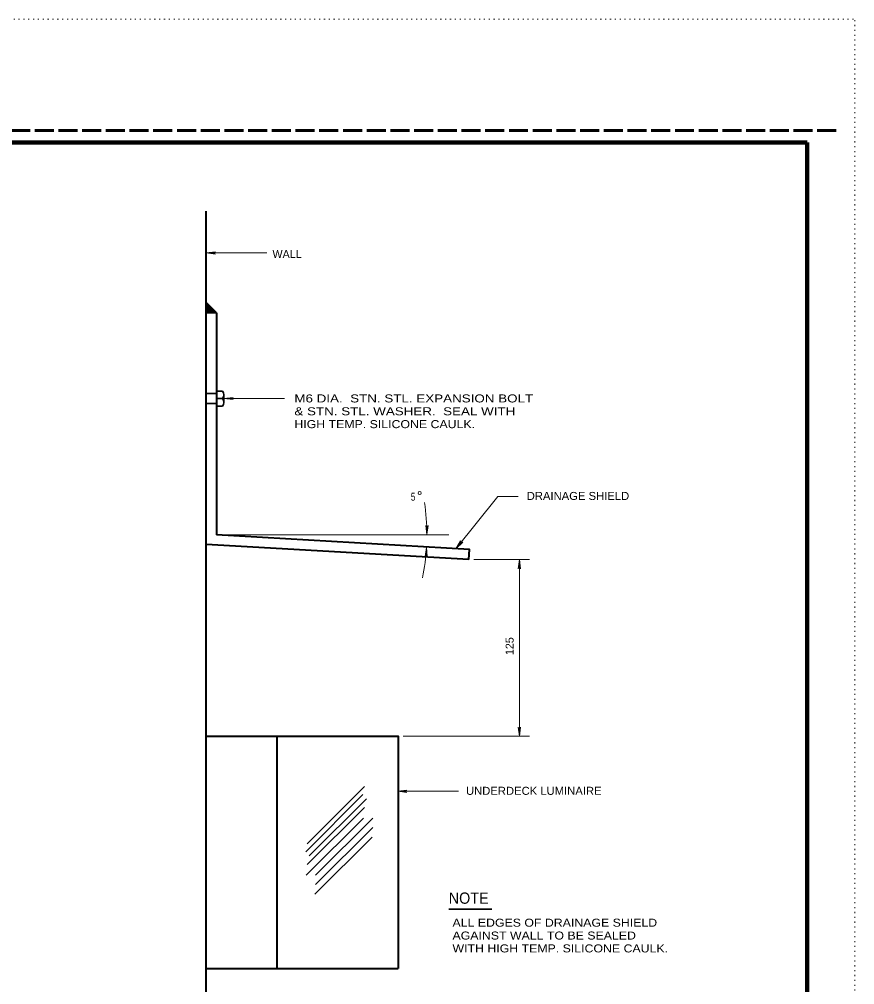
# Model space of a CAD drawing. Extents: x 312583 to 312854, y 144419 to 144597.
# Drawn here: x 312774.2 to 312853.5, y 144505.2 to 144596.8 of the extents above; entities that cross this region are included whole.
import ezdxf
from ezdxf.enums import TextEntityAlignment as Align

# ---------------------------------------------------------------- set-up
doc = ezdxf.new("R2010")
doc.units = 0
doc.header["$LTSCALE"] = 0.3
doc.linetypes.add('DOTTED', pattern=[1.5, 0.3, -1.2])
doc.linetypes.add('LONG_DASHED', pattern=[7.5, 6, -1.5])
for name, color, linetype, lineweight in [('1', 7, 'Continuous', 40), ('2', 7, 'Continuous', 13), ('62', 7, 'DOTTED', 13), ('63', 7, 'LONG_DASHED', 60)]:
    doc.layers.add(name, color=color, linetype=linetype, lineweight=lineweight)

msp = doc.modelspace()

# ---------------------------------------------------------------- linework, layer by layer
at = {"layer": '1', "lineweight": 158}
msp.add_line((312849, 144423.1446), (312849, 144585.0846), dxfattribs=at)
msp.add_lwpolyline([(312616.5, 144423.1446), (312616.5, 144585.0846), (312849, 144585.0846)], dxfattribs=at)
at = {"layer": '2', "lineweight": 40}
for p, q in [((312791.9754, 144501.9119), (312791.9754, 144578.5786)), ((312792.9337, 144568.9339), (312791.9754, 144569.8923)), ((312792.811, 144568.9339), (312791.9754, 144569.7696)), ((312792.673, 144568.9339), (312791.9754, 144569.6316)), ((312792.5197, 144568.9339), (312791.9754, 144569.4783)), ((312792.3817, 144568.9339), (312791.9754, 144569.3403)), ((312792.259, 144568.9339), (312791.9754, 144569.2176)), ((312792.1517, 144568.9339), (312791.9754, 144569.1103)), ((312792.0444, 144568.9339), (312791.9754, 144569.0029)), ((312792.9337, 144568.9339), (312791.9754, 144568.9339)), ((312792.9337, 144568.9339), (312792.9337, 144547.8506)), ((312816.892, 144545.5123), (312791.9754, 144546.9536)), ((312798.6837, 144528.7453), (312798.6837, 144506.7036)), ((312791.9754, 144506.7036), (312810.1837, 144506.7036))]:
    msp.add_line(p, q, dxfattribs=at)
at = {"layer": '2'}
for p, q in [((312791.9677, 144574.6073), (312792.834, 144574.7146)), ((312791.9677, 144574.6073), (312797.7177, 144574.6073)), ((312791.9677, 144574.6073), (312792.834, 144574.4999)), ((312792.834, 144574.7146), (312792.558, 144574.6073)), ((312792.834, 144574.4999), (312792.558, 144574.6073)), ((312792.9337, 144568.9339), (312792.9337, 144561.2673)), ((312793.6544, 144560.7996), (312794.5207, 144560.9069)), ((312793.6544, 144560.7996), (312799.4044, 144560.7996)), ((312793.6544, 144560.7996), (312794.5207, 144560.6923)), ((312794.5207, 144560.9069), (312794.2447, 144560.7996)), ((312794.5207, 144560.6923), (312794.2447, 144560.7996)), ((312815.6654, 144546.5396), (312819.6444, 144551.5076)), ((312819.6444, 144551.5076), (312821.561, 144551.5076)), ((312812.8057, 144548.7399), (312812.913, 144548.4639)), ((312812.913, 144547.8736), (312812.8057, 144548.7399)), ((312813.0204, 144548.7399), (312812.913, 144548.4639)), ((312812.913, 144547.8736), (312813.0204, 144548.7399)), ((312793.409, 144547.8506), (312814.9754, 144547.8506)), ((312812.8824, 144546.6623), (312812.729, 144545.7959)), ((312812.8824, 144546.6623), (312812.9437, 144545.7959)), ((312815.6654, 144546.5396), (312816.11, 144547.2756)), ((312815.6654, 144546.5396), (312816.3094, 144547.1606)), ((312816.11, 144547.2756), (312816.041, 144547.0073)), ((312816.3094, 144547.1606), (312816.041, 144547.0073)), ((312812.729, 144545.7959), (312812.8364, 144546.0719)), ((312812.9437, 144545.7959), (312812.8364, 144546.0719)), ((312817.3674, 144545.5123), (312822.642, 144545.5123)), ((312821.6837, 144545.5123), (312821.5764, 144544.6459)), ((312821.5764, 144544.6459), (312821.6837, 144544.9219)), ((312821.6837, 144528.7453), (312821.6837, 144545.5123)), ((312821.6837, 144545.5123), (312821.791, 144544.6459)), ((312821.791, 144544.6459), (312821.6837, 144544.9219)), ((312821.5764, 144529.6116), (312821.676, 144529.3356)), ((312821.6837, 144528.7453), (312821.5764, 144529.6116)), ((312821.791, 144529.6116), (312821.676, 144529.3356)), ((312821.6837, 144528.7453), (312821.791, 144529.6116)), ((312810.659, 144528.7453), (312822.642, 144528.7453)), ((312810.1454, 144523.5243), (312811.0117, 144523.6316)), ((312811.0117, 144523.6316), (312810.7357, 144523.5243)), ((312810.1454, 144523.5243), (312815.8954, 144523.5243)), ((312810.1454, 144523.5243), (312811.0117, 144523.4169)), ((312811.0117, 144523.4169), (312810.7357, 144523.5243))]:
    msp.add_line(p, q, dxfattribs=at)
at = {"layer": '2', "lineweight": 35}
for p, q in [((312792.9337, 144561.2673), (312791.9754, 144561.2673)), ((312793.524, 144561.5049), (312792.9337, 144561.5049)), ((312792.9337, 144560.3089), (312791.9754, 144560.3089)), ((312793.524, 144560.7843), (312792.9337, 144560.7843)), ((312793.6467, 144561.1446), (312793.6467, 144560.4239)), ((312793.524, 144560.0636), (312792.9337, 144560.0636)), ((312801.5587, 144518.5409), (312806.979, 144523.9613)), ((312801.4207, 144517.7819), (312806.841, 144523.2023)), ((312801.7504, 144517.3909), (312807.1707, 144522.8113)), ((312801.5587, 144516.5706), (312806.979, 144521.9909)), ((312801.459, 144515.5509), (312806.8794, 144520.9713)), ((312802.3484, 144515.5509), (312807.7687, 144520.9713)), ((312802.3484, 144514.6616), (312807.7687, 144520.0819)), ((312802.2794, 144513.7416), (312807.6997, 144519.1619)), ((312814.983, 144512.3386), (312819.0654, 144512.3386))]:
    msp.add_line(p, q, dxfattribs=at)
at = {"layer": '2', "lineweight": 40}
for points in [[(312816.892, 144545.5123), (312816.9457, 144546.4629), (312792.9337, 144547.8506)], [(312791.9754, 144528.7453), (312810.1837, 144528.7453), (312810.1837, 144506.7036)]]:
    msp.add_lwpolyline(points, dxfattribs=at)
at = {"layer": '2'}
msp.add_circle((312812.223, 144551.8219), 0.1457, dxfattribs=at)
at = {"layer": '2', "lineweight": 35}
for centre in [(312793.0561, 144561.1446), (312793.0561, 144560.4239)]:
    msp.add_arc(centre, 0.5906, 322.40023, 37.59977, dxfattribs=at)
at = {"layer": '2'}
for start, end in [(0.06624, 8.81172), (348.26806, 356.59225)]:
    msp.add_arc((312792.9337, 144547.8506), 19.9805, start, end, dxfattribs=at)
at = {"layer": '62'}
msp.add_line((312601.2, 144596.7846), (312853.5, 144596.7846), dxfattribs=at)
msp.add_lwpolyline([(312601.2, 144418.5846), (312853.5, 144418.5846), (312853.5, 144596.7846)], dxfattribs=at)
at = {"layer": '63'}
msp.add_line((312851.75, 144586.2246), (312583.526, 144586.2246), dxfattribs=at)

# ---------------------------------------------------------------- texts
at = {"layer": '2'}
msp.add_text('WALL', height=0.76, dxfattribs=at).set_placement((312798.2556, 144574.128))
for s, width, p in [('M6 DIA.  STN. STL. EXPANSION BOLT', 1.25, (312800.332, 144560.4229)), ('& STN. STL. WASHER.  SEAL WITH', 1.25, (312800.332, 144559.2029)), ('HIGH TEMP. SILICONE CAULK.', 1.15, (312800.332, 144557.9829)), ('5', 0.75, (312811.3874, 144551.0976)), ('DRAINAGE SHIELD', 1.05, (312822.3792, 144551.1686)), ('UNDERDECK LUMINAIRE', 1.05, (312816.6152, 144523.1829)), ('ALL EDGES OF DRAINAGE SHIELD', 1.15, (312815.3357, 144510.6663)), ('AGAINST WALL TO BE SEALED', 1.15, (312815.3357, 144509.4463)), ('WITH HIGH TEMP. SILICONE CAULK.', 1.15, (312815.3357, 144508.2263))]:
    msp.add_text(s, height=0.76, dxfattribs=dict(at, width=width)).set_placement(p)
msp.add_text('125', height=0.76, rotation=90, dxfattribs=at).set_placement((312821.138, 144536.4429))
at = {"layer": '2', "width": 0.95}
msp.add_text('NOTE', height=1.07, dxfattribs=at).set_placement((312816.8716, 144512.842), align=Align.CENTER)

doc.saveas('drawing.dxf')
